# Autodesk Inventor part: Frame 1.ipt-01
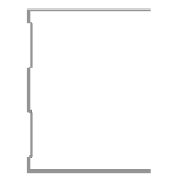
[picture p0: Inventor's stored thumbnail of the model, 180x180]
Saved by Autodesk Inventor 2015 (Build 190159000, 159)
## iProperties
Created: 2015-04
Part Number: Frame 1.ipt-01
Material: Aluminum 6061
Document SubType Name: Modeling
Standard: Unnamed
Designer: suporte
Language: en-US
Size Designation: (Unnamed 1)
Categories: <MemberInstance><Categories><Category DisplayName="Structural Shapes" InternalName="089c4875-fa83-4c05-b084-43b9cc11f5ed" Mnemonic="GRDR"><CategoryParameter Dis
Density: 2.7 g/cm^3
Appearance: Aluminum - Flat
_CCFamilyMember: 1
_CCFamilyDisplayName: Frame 1
_FrameMemberDoc: Frame Member File
_Version: 15.0.0
_GetPNFromCC: 1
IsCustomPart: 1
Author: suporte
G_L: 600,000 mm
G_W: 70,000 mm
G_H: 75,000 mm
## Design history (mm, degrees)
node "Start Plane"
node "End Plane"
sketch "Sketch"
  geometry: L1 (34.6, 37.5)-(34.6, 36.7); L2 (34.6, 36.7)-(-34.6, 36.7); L3 (-34.6, -36.7)-(34.6, -36.7); L4 (34.6, -36.7)-(34.6, -37.5); L5 (34.6, -37.5)-(-35.4, -37.5); L6 (-35.4, 37.5)-(34.6, 37.5); L7 (-34.6, 36.7)-(-34.6, 31.7); L8 (-34.6, 31.7)-(-33.4, 30.5); L9 (-33.4, 30.5)-(-33.4, 10.746); L10 (-33.4, 10.746)-(-34.6, 9.546); L11 (-34.6, 9.546)-(-34.6, -9.546); L12 (-34.6, -9.546)-(-33.4, -10.746); L13 (-33.4, -10.746)-(-33.4, -30.5); L14 (-33.4, -30.5)-(-34.6, -31.7); L15 (-34.6, -31.7)-(-34.6, -36.7); L16 (-35.4, -37.5)-(-35.4, -31.369); L17 (-35.4, -31.369)-(-34.2, -30.169); L18 (-34.2, -30.169)-(-34.2, -11.077); L19 (-34.2, -11.077)-(-35.4, -9.877); L20 (-35.4, -9.877)-(-35.4, 9.877); L21 (-35.4, 9.877)-(-34.2, 11.077); L22 (-34.2, 11.077)-(-34.2, 30.169); L23 (-34.2, 30.169)-(-35.4, 31.369); L24 (-35.4, 31.369)-(-35.4, 37.5); L25 (-35.4, 0)-(30.37, 0); 3 further points
  constraints: 50 end point, 10 point on line, 9 parallel, 5 perpendicular, 4 equal length, 3 midpoint, 3 vertical, 2 vertical alignment, 1 collinear, 1 horizontal, 1 horizontal alignment
  dimensions: "d3" = 0.8 distance of L1.start L1.end; "d5" = 75 distance between parallel lines of L5 L6; "d6" = 0.8 distance between parallel lines of L24 L7; "d7" = 0.8 distance between parallel lines of L8 L23; "d8" = 0.8 distance between parallel lines of L22 L9; "d9" = 0.8 distance between parallel lines of L17 L14; "d10" = 0.8 distance between parallel lines of L13 L18; "d11" = 0.8 distance between parallel lines of L12 L19; "d12" = 0.8 distance between parallel lines of L21 L10; "d13" = 5 distance of L2.end L7.end; "d15" = 135 deg angle of L9 L8; "d16" = 2 distance between parallel lines of L24 L9; "d17" = 70 distance of L6.start L1.start
extrude "Body" join sketch "Sketch" stored distance "d24" = 0.13; taper "d25" = 0 deg
node "Driven Length"
  sketch "Sketch8"
    geometry: L1 (0, 0)-(10, 0) reference
    constraints: 2 end point, 1 horizontal
  workplane "Work Plane6"
  sketch "Sketch9"
    geometry: L1 (-2, 0)-(12, 0) reference; L2 (-2, 600)-(12, 600) reference
    dimensions: "d27" = 600 distance between parallel lines of L1 L2 (derived)
body "Solid1"
other parameters: "G_OFFSET_START" = 0 [user parameter; used in 1 equation term], "G_OFFSET_END" = 0 [user parameter; used in 1 equation term], "d22" = 0 (computed from G_OFFSET_START), "G_L" = 600 (= d27) [user parameter], "d32" = 90 deg
